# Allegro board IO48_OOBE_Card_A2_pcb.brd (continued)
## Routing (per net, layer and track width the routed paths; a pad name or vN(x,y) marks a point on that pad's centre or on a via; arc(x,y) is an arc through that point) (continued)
E_RXD0: length 7.5
  TOP w0.142: R31.2 50.72,80.03 v1(50.72,79.58) 50.72,79.15 50.64,79.07 U1.32
  BOTTOM w0.142: v1(50.72,79.58) 50.59,79.71 R32.1 51.04,80.53 51.23,80.72 51.23,82.88 51.04,83.07 R12.1
E_RXD1: length 7.6
  TOP w0.142: R29.2 v1(51.74,79.58) 51.1,78.95 51.1,78.18 51.14,78.14 U1.31
  BOTTOM w0.142: v1(51.74,79.58) 51.86,79.71 R30.1 52.31,80.53 52.5,80.72 52.5,82.88 52.31,83.07 R13.1
E_RXD2: length 7.6
  TOP w0.142: U1.28 52.64,78.96 52.75,79.07 v1(52.75,79.58) 53.01,79.83 R27.2
  BOTTOM w0.142: v1(52.75,79.58) 53.13,79.96 R28.1 53.58,80.53 53.77,80.72 53.77,82.88 53.58,83.07 R14.1
E_RXD3: length 8.1
  TOP w0.142: R25.2 54.02,80.03 54.02,79.83 v1(53.77,79.58) 53.01,78.82 53.01,78.18 53.14,78.05 U1.27
  BOTTOM w0.142: v1(53.77,79.58) 54.4,80.22 R26.1 54.85,80.53 55.04,80.72 55.04,82.88 54.85,83.07 R15.1
EN: length 3
  BOTTOM w0.127: U5.20 19.47,53.3 18.91,53.86 R5286.1
ENET_1.2V_AVDDL: length 9.6
  TOP w0.254: U1.4 v1(50.14,69.67) ; U1.9 v1(52.64,69.8)
  BOTTOM w0.381: v1(52.64,69.8) 53.01,70.17 C931.2 51.93,70.5 C23.1 50.78,70.5 C25.2 49.7,70.11 v1(50.14,69.67)
  BOTTOM w0.508: L4.2 C23.1
ENET_1.2V_AVDLL_PLL: length 6.9
  TOP w0.254: U1.44 47.02,73.38 v1(46.91,73.48)
  BOTTOM w0.508: L3.2 C18.1 45.77,71.96 46.4,72.6 C20.2 46.91,72.66 v1(46.91,73.48)
ENET_1.2V_DVDDL: length 14.2
  TOP w0.254: U1.30 v1(51.64,78.56) ; v1(56.31,73.48) 55.92,73.88 U1.18 ; U1.14 55.12,71.88 v1(55.93,71.07) ; v1(56.18,76.63) 55.93,76.38 U1.23 ; v1(53.77,78.56) 53.64,78.44 U1.26 ; v1(46.53,76.15) 46.8,75.88 U1.39
  BOTTOM w0.508: C936.2 55.55,71.45 v1(55.93,71.07) ; v1(51.64,78.56) 51.61,78.53 C932.2 ; C933.2 v1(53.77,78.56) ; v1(56.18,76.63) 56.12,76.69 C934.2 56.12,78.25 ; C935.2 56.12,73.68 v1(56.31,73.48) ; v1(46.53,76.15) 46.97,76.15 C31.2
  vias: v1(55.67,79.71)
ENET_1.8V_DVDDH: length 19.5
  TOP w0.254: U1.40 46.77,75.38 v1(46.53,75.14) ; U1.16 55.52,72.88 56.05,72.34 v1(56.44,72.34) ; U1.34 v1(49.64,78.56)
  TOP w0.381: R37.1 v1(42.85,74.88) ; R18.1 v1(58.34,70.75) ; v1(55.55,81.36) 55.36,81.17 R25.1 R27.1 R29.1 R31.1 R33.1 R35.1 47.48,81.17 v1(47.16,81.49) ; v1(59.86,76.09) R22.1
  BOTTOM w0.508: v1(46.53,75.14) 47.04,74.63 C938.2 ; C939.2 56.5,72.41 v1(56.44,72.34) ; v1(49.64,78.56) 49.7,78.5 C17.2 48.24,77.87
  vias: v1(47.55,77.68) v1(48.18,78.95)
ENET_3.3V_AVDDH: length 8.7
  TOP w0.254: U1.12 54.14,70.06 v1(54.4,69.8) ; U1.1 v1(48.64,69.72)
  BOTTOM w0.381: C937.2 54.28,69.93 v1(54.4,69.8) ; C13.2 48.43,69.93 v1(48.64,69.72)
  BOTTOM w0.508: L1.2 C11.1 55.93,69.55 54.97,70.5 C937.2
ENET_GTX_CLK: length 5.3
  BOTTOM w0.142: J1.15 19.93,67.83 20.37,67.39 21.62,67.39 R5311.2
ENET_INTN: length 35.7
  TOP w0.142: U1.38 47.32,76.38 46.91,76.79 45.64,76.79 45.13,76.28 R10.2 44.56,75.83 44.37,75.64 42.34,75.64 41.96,76.02 v1(41.96,76.79)
  L3_SIG w0.155: v1(24.3,69.29) 24.68,69.67 24.68,69.8 27.35,72.47 27.35,73.87 28.88,75.39 40.56,75.39 v1(41.96,76.79)
  BOTTOM w0.142: J1.27 19.87,70.83 20.11,71.07 22.53,71.07 v1(24.3,69.29)
ENET_LED1: length 8.2
  TOP w0.142: v1(59.8,75.2) R22.2 R23.1 58.15,74.06 57.07,72.98 56.05,72.98 55.65,73.38 U1.17
  BOTTOM w0.142: v1(59.8,75.2) 60.2,75.6 Q6.1
ENET_LED2: length 11.6
  TOP w0.142: U1.15 55.38,72.38 56.12,71.64 R18.2 R19.1 60.5,74.25 60.75,74.5 61.87,74.5 Q4.1
ENET_MDC: length 47.6
  TOP w0.142: v1(31.54,82.88) 33.45,82.88 34.62,81.71 39.32,81.71 42.59,78.44 44.37,78.44 44.56,78.63 R4.2 46.02,79.07 46.78,78.31 48.12,78.31 48.64,77.79 U1.36
  L3_SIG w0.155: v1(31.54,82.88) 30.73,82.07 30.73,81.84 30.17,81.28 27.66,81.28 25.13,78.76 23.22,78.76 22.65,78.18 18.84,78.18 17.06,76.41 11.1,76.41 10.59,75.9 v1(10.59,75.39)
  BOTTOM w0.142: J1.50 11.93,76.33 11.86,76.41 11.22,76.41 10.59,75.77 v1(10.59,75.39)
ENET_MDIO: length 34.7
  TOP w0.142: U1.37 47.33,76.88 46.53,77.68 R6.2 44.56,77.1 44.46,77 42.76,77 41.7,78.06 41.7,78.56 39.14,81.13 34.06,81.13 33.32,81.87 v1(31.54,81.87)
  L3_SIG w0.155: v1(20.24,76.15) 21,76.91 24.05,76.91 25.32,78.18 27.86,80.72 30.4,80.72 v1(31.54,81.87)
  BOTTOM w0.142: J1.49 20.06,76.33 v1(20.24,76.15)
ENET_RSET: length 4.1
  TOP w0.142: U1.48 47.39,71.38 47.08,71.07 46.45,71.07 45.82,71.71 45.2,71.71 R17.1
ENET_RSTN: length 20.1
  TOP w0.142: R5287.2 v1(31.92,81.04) ; v1(45.39,74.25) 45.51,74.12 47.04,74.12 47.29,74.38 U1.42
  BOTTOM w0.142: v1(31.92,81.04) 32.94,80.03 32.94,79.58 36.88,75.64 43.99,75.64 v1(45.39,74.25)
ENET_RX_CLK: length 58.2
  L3_SIG w0.155: v1(37.13,82.88) 41.7,82.88 41.96,82.63 41.96,82.05 41.8,81.89 39.57,81.89 39.42,81.74 39.42,81.43 39.57,81.28 41.55,81.28 41.7,81.12 41.7,80.81 41.55,80.66 39.57,80.66 39.42,80.5 39.42,80.19 39.57,80.04 40.41,80.04 40.56,79.88 40.56,78.43 40.41,78.28 39.52,78.28 39.37,78.12 39.37,77.81 39.52,77.66 40.41,77.66 40.56,77.5 40.56,76.41 40.05,75.9 28.5,75.9 26.84,74.25 26.84,72.72 22.14,68.02 v1(21,68.02)
  BOTTOM w0.142: v1(21,68.02) 20.49,68.02 20.19,68.33 J1.17 ; v1(37.13,82.88) 37.51,83.26 46.66,83.26 47.35,83.96 R8.2
ENET_RX_DV: length 58.4
  L3_SIG w0.155: v1(10.59,69.04) 10.71,68.91 11.6,68.91 12.18,69.48 12.39,69.48 13.2,68.68 13.42,68.68 13.64,68.9 13.64,69.12 12.83,69.92 12.83,70.14 13.13,70.44 14.4,70.44 14.78,70.06 16.81,70.06 17.06,69.8 18.46,69.8 18.76,70.1 18.98,70.1 19.91,69.17 20.13,69.17 20.35,69.39 20.35,69.61 19.42,70.54 19.42,70.76 19.99,71.33 23.16,71.33 24.3,72.47 24.3,73.49 24.46,73.65 24.96,73.65 25.11,73.8 25.11,74.11 24.96,74.27 24.46,74.27 24.3,74.42 24.3,74.88 28.62,79.2 33.83,79.2 34.72,80.09 v1(34.72,82.76)
  BOTTOM w0.142: J1.18 11.81,68.33 11.6,68.53 11.1,68.53 v1(10.59,69.04) ; R11.2 49.32,84.41 49.2,84.53 47.04,84.53 46.27,83.77 36.88,83.77 36.11,83.01 34.97,83.01 v1(34.72,82.76)
ENET_RXD0: length 58
  L3_SIG w0.155: v1(21,69.33) 22.69,69.33 26.21,72.85 26.21,74.63 27.99,76.41 30.02,76.41 30.91,77.29 32.3,77.29 33.07,76.53 34.3,76.53 34.45,76.69 34.45,77.27 34.61,77.42 34.92,77.42 35.07,77.27 35.07,76.69 35.23,76.53 35.54,76.53 35.69,76.69 35.69,77.27 35.85,77.42 36.16,77.42 36.31,77.27 36.31,76.69 36.47,76.53 38.78,76.53 38.91,76.66 38.91,77.27 38.75,77.42 37.97,77.42 37.77,77.63 37.77,78.4 37.92,78.56 38.75,78.56 38.91,78.71 38.91,79.02 38.75,79.18 37.92,79.18 37.77,79.33 37.77,79.64 37.92,79.8 38.75,79.8 38.91,79.95 38.91,80.26 38.75,80.42 37.92,80.42 37.77,80.57 37.77,80.88 37.92,81.04 38.5,81.04 38.66,81.19 38.66,81.5 38.5,81.66 37.92,81.66 37.77,81.81 37.77,82.09 37.61,82.25 36.9,82.25 36.75,82.4 36.75,82.5 36.11,83.14 v1(36.11,84.03)
  BOTTOM w0.142: v1(36.11,84.03) 36.37,84.28 46.02,84.28 46.78,85.04 50.32,85.04 50.59,84.77 R12.2 ; J1.21 v1(21,69.33)
ENET_RXD1: length 57.7
  L3_SIG w0.155: v1(33.7,84.03) 33.7,83.39 33.55,83.23 33.3,83.23 33.15,83.08 33.15,82.77 33.3,82.62 33.93,82.62 34.08,82.46 34.08,82.15 33.93,82 33.3,82 33.15,81.84 33.15,81.53 33.3,81.38 33.8,81.38 33.96,81.22 33.96,80.09 33.58,79.71 28.37,79.71 23.8,75.14 23.8,72.72 22.91,71.83 19.73,71.83 18.21,70.31 17.32,70.31 17.06,70.56 15.03,70.56 14.65,70.94 12.75,70.94 v1(11.35,69.55)
  BOTTOM w0.142: R13.2 51.86,85.04 51.35,85.55 46.53,85.55 45.77,84.79 35.73,84.79 35.35,84.41 35.35,83.9 34.97,83.52 34.21,83.52 v1(33.7,84.03) ; v1(11.35,69.55) 11.57,69.33 J1.22
ENET_RXD2: length 58
  L3_SIG w0.155: v1(21,70.56) 23.16,70.56 25.66,73.07 25.66,75.48 28.88,78.69 32.56,78.69 33.19,78.06 36.81,78.06 37,78.25 37,78.6 36.78,78.82 35.71,78.82 35.46,79.07 35.46,79.41 35.62,79.57 37.1,79.57 37.26,79.72 37.26,80.03 37.1,80.19 35.62,80.19 35.46,80.34 35.46,80.8 35.62,80.95 36.85,80.95 37.05,81.15 37.05,81.37 36.85,81.57 35.62,81.57 35.46,81.73 35.46,83.28 v1(34.72,84.03)
  BOTTOM w0.142: R14.2 53.13,85.42 52.5,86.06 46.4,86.06 45.64,85.3 35.23,85.3 34.72,84.79 v1(34.72,84.03) ; J1.25 20,70.33 20.24,70.56 v1(21,70.56)
ENET_RXD3: length 58.3
  L3_SIG w0.155: v1(10.59,70.06) 10.84,70.06 12.24,71.45 14.14,71.45 15.03,72.34 16.05,72.34 17.57,70.82 17.95,70.82 20.11,72.98 20.88,72.98 28.11,80.22 32.18,80.22 32.55,80.58 32.55,83.34 32.69,83.48 v1(32.69,84.03)
  BOTTOM w0.142: v1(32.69,84.03) 34.46,85.8 45.51,85.8 46.22,86.52 53.69,86.52 54.4,85.8 R15.2 ; v1(10.59,70.06) 10.84,70.06 11.11,70.33 J1.26
ENET_TX_EN: length 59.9
  TOP w0.142: v1(58.34,77.68) 57.2,77.68 55.8,79.07 54.78,79.07 54.4,78.69 54.4,78.06 54.14,77.8 U1.25
  L3_SIG w0.155: v1(58.34,77.68) 58.72,77.29 58.72,75.14 57.2,73.61 57.2,72.34 56.63,71.77 55.86,71.77 55.16,71.07 45.51,71.07 45.26,71.33 43.1,71.33 42.48,70.7 39.84,70.7 39.7,70.56 32.43,70.56 31.29,69.42 29.77,69.42 27.99,67.64 25.95,67.64 25.07,66.75 23.41,66.75 23.03,66.37 20.37,66.37 18.84,67.9 15.03,67.9 14.93,67.8 v1(14.3,67.8)
  BOTTOM w0.142: v1(14.3,67.8) 14.27,67.83 J1.16
ENET_TXD0: length 59.5
  TOP w0.142: U1.19 56.31,74.38 56.56,74.12 57.32,74.12 58.21,75.01 58.21,76.15 v1(57.58,76.79)
  L3_SIG w0.155: v1(57.58,76.79) 54.02,80.34 47.16,80.34 46.91,80.09 46.91,78.98 46.76,78.82 44.52,78.82 44.37,78.67 44.37,78.36 44.52,78.2 46.76,78.2 46.91,78.05 46.91,77.55 46.78,77.42 44.5,77.42 44.24,77.17 44.24,75.52 42.97,74.25 42.21,74.25 42.08,74.37 32.43,74.37 31.04,72.98 29,72.98 28.49,72.47 28.49,71.96 26.34,69.8 v1(26.34,69.29)
  BOTTOM w0.142: v1(26.34,69.29) 26.34,68.91 25.45,68.02 22.27,68.02 21.64,68.66 20.49,68.66 20.33,68.83 J1.19
ENET_TXD1: length 59.9
  TOP w0.142: U1.20 55.68,74.88 55.8,74.75 v1(57.07,74.75)
  L3_SIG w0.155: v1(57.07,74.75) 56.66,74.75 54.76,72.85 46.78,72.85 45.77,71.83 42.72,71.83 42.19,71.3 40.38,71.3 40.15,71.54 40.15,72.06 39.99,72.21 39.68,72.21 39.53,72.06 39.53,71.23 39.37,71.07 39.06,71.07 38.91,71.23 38.91,72.06 38.75,72.21 38.44,72.21 38.29,72.06 38.29,71.23 38.13,71.07 37.82,71.07 37.67,71.23 37.67,72.06 37.51,72.21 37.2,72.21 37.05,72.06 37.05,71.23 36.89,71.07 36.58,71.07 36.43,71.23 36.43,72.06 36.27,72.21 35.96,72.21 35.81,72.06 35.81,71.23 35.65,71.07 35.34,71.07 35.19,71.23 35.19,72.06 35.03,72.21 34.72,72.21 34.57,72.06 34.57,71.23 34.41,71.07 31.92,71.07 31.67,70.82 30.4,70.82 27.73,68.15 23.92,68.15 22.65,66.88 20.62,66.88 19.1,68.4 14.69,68.4 v1(14.27,68.83)
  BOTTOM w0.142: J1.20 v1(14.27,68.83)
ENET_TXD2: length 59.7
  TOP w0.142: U1.21 55.81,75.38 56.05,75.14 56.56,75.14 57.07,75.64 v1(57.58,75.64)
  L3_SIG w0.155: v1(25.32,69.29) 25.32,69.67 27.99,72.34 27.99,72.72 28.75,73.48 30.65,73.48 32.05,74.88 41.2,74.88 41.83,75.52 42.85,75.52 43.61,76.28 43.61,79.28 43.76,79.44 46.12,79.44 46.27,79.59 46.27,79.9 46.12,80.06 43.76,80.06 43.61,80.21 43.61,80.6 43.86,80.85 55.42,80.85 56.56,79.71 56.56,78.56 58.21,76.91 58.21,76.28 v1(57.58,75.64)
  BOTTOM w0.142: v1(25.32,69.29) 24.68,68.66 22.65,68.66 21.38,69.93 20.37,69.93 20.27,69.83 J1.23
ENET_TXD3: length 59
  TOP w0.142: v1(56.31,75.64) 56.08,75.88 U1.22
  L3_SIG w0.155: v1(56.31,75.64) 55.93,75.64 55.8,75.52 55.8,74.93 55.65,74.77 55.18,74.77 55.02,74.93 55.02,75.36 54.87,75.52 54.3,75.52 54.15,75.36 54.15,73.61 54.02,73.48 53.13,73.48 52.88,73.74 52.88,75.26 52.75,75.39 52.14,75.39 51.99,75.24 51.99,73.61 51.74,73.36 50.21,73.36 49.96,73.61 49.96,75.25 49.8,75.41 48.84,75.41 48.69,75.25 48.69,74.25 48.56,74.12 46.53,74.12 46.02,73.61 45.51,73.61 44.24,72.34 41.2,72.34 40.56,72.98 32.94,72.98 31.29,71.33 30.15,71.33 27.48,68.66 23.67,68.66 22.4,67.39 20.88,67.39 19.35,68.91 15.19,68.91 v1(14.27,69.83)
  BOTTOM w0.142: J1.24 v1(14.27,69.83)
ENET_VDD1.2V: length 7.7
  TOP w0.254: U62.2 61.71,86.56 C930.2 ; U62.1 61.26,86.06
  TOP w0.381: R699.1 v1(63.17,89.99) ; R5265.2 v1(61.9,89.99)
  BOTTOM w0.508: L4.1 v1(48.69,67.52) ; v1(41.58,72.98) 40.69,72.09 L3.1
  vias: v1(60.88,80.6) v1(61.13,81.36) v1(61.9,81.49) v1(61.9,80.6)
ENET_XI: length 3.4
  TOP w0.142: R21.2 46.53,72.34 46.56,72.38 U1.46
FPGA_JTAG_TCK: length 16.4
  L6_SIG w0.155: v1(19.61,86.57) 23.57,82.6 v1(23.57,79.3)
  BOTTOM w0.142: J1.55 19.89,77.83 20.11,78.06 R693.1 21.83,78.63 22.02,78.82 23.08,78.82 v1(23.57,79.3) ; v1(19.61,86.57) 18.98,86.57 18.91,86.5 R117.1
FPGA_JTAG_TDI: length 23.1
  TOP w0.142: R681.1 8.02,76.96 7.95,77.04 v1(7.41,77.04)
  L6_SIG w0.155: v1(13.89,88.22) 13.89,86.18 6.65,78.95 6.65,77.8 v1(7.41,77.04)
  BOTTOM w0.142: J1.56 11.89,77.83 11.35,77.29 10.65,77.29 R686.2 9.13,77.04 v1(7.41,77.04) ; R121.1 v1(13.89,88.22)
FPGA_JTAG_TDO: length 39.3
  L6_SIG w0.155: v1(7.41,78.31) 7.41,78.95 14.42,85.95 14.42,88.62 18.21,92.41 29.64,92.41 v1(31.23,90.82)
  BOTTOM w0.142: R123.1 v1(31.23,90.82) ; J1.58 11.71,78.34 11.48,78.56 10.65,78.56 R688.2 9.13,78.31 v1(7.41,78.31)
FPGA_JTAG_TMS: length 15.6
  TOP w0.142: R682.1 18.84,78.06 18.78,78.12 R687.2 18.06,78.69 v1(17.7,78.34)
  L6_SIG w0.155: v1(17.7,88.22) 17.7,85.42 18.97,84.15 18.97,80.47 17.7,79.2 v1(17.7,78.34)
  BOTTOM w0.142: R119.1 v1(17.7,88.22) ; J1.57 v1(17.7,78.34)
FT232R_3V3OUT: length 7.1
  TOP w0.254: U9.16 73.76,84.25 74.14,84.64 v1(74.14,85.14)
  BOTTOM w0.508: v1(74.14,85.14) 74.14,85.82 C55.2 73.9,86.5 74.34,86.95 C56.1 v1(75.1,85.93) ; v1(75.99,81.1) 75.55,81.1 R97.1
FT232R_RXD: length 4.3
  TOP w0.142: U9.2 70.04,78.95 69.6,78.5 68.83,78.5 67.87,77.53 U65.4
FT232R_TXD: length 3.5
  TOP w0.142: U63.2 67.89,83.37 68.12,83.14 68.12,81.88 68.25,81.75 U9.30
FT232R_VCCIO: length 20
  TOP w0.254: v1(69.39,79.08) 69.54,79.23 U9.1
  TOP w0.305: v1(75.87,80.15) R105.2
  TOP w0.381: R5284.1 v1(64.37,86.95) ; v1(67.61,80.22) C945.1 66.91,79.48 67.56,78.83 U65.5 ; v1(72.69,89.87) 71.74,89.87 R5271.1 ; U64.5 70.93,90.14 71.36,90.57 C944.1 v1(70.53,91.01)
  TOP w0.508: v1(69.1,90.92) D5.A D4.A
  BOTTOM w0.508: v1(69.39,79.08) 69.54,79.23 C57.2 69.73,79.77 70.68,78.82 C58.1 C919.1 74.15,78.82 R97.2 75.26,79.54 v1(75.87,80.15)
HPS_JTAG_TCK: length 20.9
  L6_SIG w0.155: v1(19.61,85.42) 22.65,82.37 v1(22.65,73.87)
  BOTTOM w0.142: v1(22.65,73.87) 22.08,73.29 R692.1 21.32,72.98 20.37,72.98 20.22,72.83 J1.35 ; v1(19.61,85.42) 16.94,85.42 16.43,85.93 R118.1
HPS_JTAG_TDI: length 26.4
  L6_SIG w0.155: v1(15.16,88.22) 15.16,85.68 8.68,79.2 8.68,73.99 v1(7.41,72.72)
  BOTTOM w0.142: J1.38 10.87,73.33 10.84,73.36 R689.2 9.76,73.8 9.57,73.99 8.15,73.99 7.41,73.26 v1(7.41,72.72) ; R122.1 v1(15.16,88.22)
HPS_JTAG_TDO: length 30.6
  TOP w0.142: R691.2 17.32,73.55 v1(17.54,73.33)
  L6_SIG w0.155: v1(28.43,90.38) 27.92,90.38 27.41,89.87 20.88,89.87 18.97,87.96 18.97,84.91 19.48,84.41 19.48,80.22 18.34,79.07 18.34,77.8 16.68,76.15 16.68,74.19 v1(17.54,73.33)
  BOTTOM w0.142: J1.37 v1(17.54,73.33) ; R124.1 v1(28.43,90.38)
HPS_JTAG_TMS: length 25
  L6_SIG w0.155: v1(16.43,88.22) 16.43,86.06 9.45,79.07 9.45,75.14 9.33,75.02 v1(9.33,71.33)
  BOTTOM w0.142: v1(9.33,71.33) 9.76,71.76 R690.2 10.51,72.83 J1.36 ; R120.1 v1(16.43,88.22)
HPS_LED0: length 13.5
  TOP w0.142: R681.2 9.51,77.85 10.55,78.9 12.47,78.9 12.7,79.13 Q1.1 13.67,79.77 14,79.44 14,78.45 16.62,75.83 v1(17.54,75.83)
  BOTTOM w0.142: J1.47 v1(17.54,75.83)
HPS_LED1: length 9.2
  TOP w0.142: R682.2 18.84,75.64 18.46,75.26 14.27,75.26 v1(14.2,75.33) 14.2,75.71 13.82,76.09 Q3.1
  BOTTOM w0.142: J1.46 v1(14.2,75.33)
HPS_LED2: length 7.5
  TOP w0.142: v1(11.48,75.83) 11.48,75.64 12.62,74.5 13.26,74.5 13.76,73.99 13.76,72.85 13.51,72.6 13,72.6 12.7,72.3 Q2.1
  BOTTOM w0.142: J1.48 v1(11.48,75.83)
HPS_OSC_CLK: length 2.9
  BOTTOM w0.142: J1.45 19.93,75.33 19.99,75.39 R5291.2
HPS_OSC_CLK_1.8V: length 6.3
  BOTTOM w0.508: 28.75,75.2 R131.1 ; R5309.2 31.86,76.02 C955.1 31.29,75.71 C953.2 28.56,75.71
HPS_PB0: length 13.8
  TOP w0.142: U69.4 v1(28.51,67.37)
  BOTTOM w0.142: v1(28.51,67.37) 28.5,67.39 28.5,69.67 27.99,70.18 24.56,70.18 23.08,71.66 20.17,71.66 20,71.83 J1.31
HPS_PB1: length 31.2
  TOP w0.142: v1(10.33,71.33) 11.1,70.56 11.3,70.56 12.87,68.99 12.87,68.02 14.02,66.88 15.41,66.88 16.23,66.07 17.2,66.07 17.66,65.61 20.24,65.61 22.65,68.02 28.04,68.02 28.52,68.51 30.98,68.51 31.86,67.63 31.86,66.42 32.32,65.96 U70.4
  BOTTOM w0.142: v1(10.33,71.33) 10.84,71.83 J1.32
HPS_RESETN: length 4.3
  TOP w0.142: R683.1 R7.2 21.25,77.29 21,77.55 v1(20.49,77.55)
  BOTTOM w0.142: v1(20.49,77.55) 20.28,77.33 J1.53
HPS_RESETN_1: length 4.9
  TOP w0.142: R685.1 25.7,76.02 25.95,76.28 25.95,77.55 25.7,77.8 25.5,77.8 25.17,78.13 25.17,79.09 25.28,79.2 U68.2
I2C1_SCL: length 22.4
  TOP w0.142: R695.2 14.25,72.28 v1(14.2,72.33)
  L3_SIG w0.155: v1(14.2,72.33) 9.96,72.33 8.86,73.43 8.86,83.09 7.29,84.66 J2.1
  BOTTOM w0.142: J1.34 v1(14.2,72.33)
I2C1_SDA: length 27.7
  TOP w0.142: v1(17.54,72.33) 17.47,72.41 R694.2
  L3_SIG w0.155: v1(17.54,72.33) 16.63,73.24 10,73.24 9.45,73.8 9.45,83.64 8.43,84.66 8.43,88.47 J2.2
  BOTTOM w0.142: J1.33 v1(17.54,72.33)
INTVCC: length 1.8
  TOP w0.381: U15.C3 v1(47.8,89.99)
  BOTTOM w0.381: v1(47.8,89.99) 48.17,89.99 48.29,90.12 R671.2
LINK_LED: length 29.8
  TOP w0.254: L10.2 v1(65.83,70.06)
  L6_SIG w0.254: v1(65.83,70.06) 65.83,69.42 66.09,69.17 66.09,59.77 66.98,58.88 74.98,58.88 77.64,56.21 77.64,53.14 J3.17
LOGIC0A: length 3.9
  TOP w0.142: R113.2 24.3,82.88 23.2,83.99 J8.30
LOGIC0B: length 3.6
  TOP w0.142: J8.32 22.56,83.74 23.03,83.26 R114.2
LOGIC1: length 3.7
  TOP w0.142: J8.34 21.93,84.5 22.14,84.28 22.14,83.01 21.76,82.63 R115.2
MDI_HPS_N0: length 21.9
  TOP w0.112: U1.3 49.64,70.07 49.56,69.98 49.56,67.92 56.24,61.23 56.24,58.94 59.44,55.74 60.93,55.74 61.02,55.74 61.39,56.11 J3.10
MDI_HPS_N1: length 33.4
  TOP w0.112: J3.5 63.93,56.59 64.49,57.15 65.14,57.15 65.25,57.04 65.25,56.21 65.07,56.04 65.07,55.63 65.25,55.45 65.25,55.2 65.07,55.02 65.07,54.69 65.25,54.51 65.25,53.3 64.68,52.73 63.43,52.73 62.73,53.43 62.73,54.13 62.91,54.31 62.91,54.77 62.73,54.94 62.73,56.04 62.91,56.21 62.91,56.67 62.73,56.85 62.73,57.84 62.2,58.37 59.77,58.37 58.21,59.93 58.21,60.15 57.96,60.4 57.74,60.4 57.45,60.69 57.45,61.8 51.06,68.2 51.06,69.98 51.14,70.07 U1.6
MDI_HPS_N2: length 19.3
  TOP w0.112: U1.8 52.14,70.07 52.06,69.98 52.06,69.23 59.99,61.29 59.99,60.36 60.64,59.72 61.72,59.72 62.91,60.91 63.67,60.91 63.93,61.17 J3.2
MDI_HPS_N3: length 17.8
  TOP w0.112: J3.9 62.07,61.6 62.32,61.6 62.86,62.14 62.86,65.87 61.65,67.08 55.98,67.08 53.56,69.51 53.56,69.98 53.64,70.07 U1.11
MDI_HPS_P0: length 21.9
  TOP w0.112: J3.11 60.79,55.41 59.31,55.41 55.91,58.81 55.91,61.09 49.23,67.78 49.23,69.98 49.14,70.07 U1.2
MDI_HPS_P1: length 33.5
  TOP w0.112: U1.5 50.64,70.07 50.73,69.98 50.73,68.06 57.12,61.66 57.12,60.56 59.63,58.04 62.06,58.04 62.4,57.7 62.4,53.29 63.29,52.4 64.82,52.4 65.58,53.16 65.58,57.18 65.27,57.48 64.31,57.48 J3.4
MDI_HPS_P2: length 19.2
  TOP w0.112: U1.7 51.64,70.07 51.73,69.98 51.73,69.09 59.66,61.16 59.66,60.23 60.5,59.39 61.86,59.39 63.05,60.58 63.24,60.58 J3.3
MDI_HPS_P3: length 17.8
  TOP w0.112: U1.10 53.14,70.07 53.23,69.98 53.23,69.37 55.74,66.85 55.84,66.75 56.11,66.75 61.52,66.75 62.53,65.74 62.53,62.27 62.19,61.93 61.66,61.93 61.39,62.2 J3.8
MICRO_USB_PGND:
  vias: v1(39.04,50.85) v1(39.04,49.81) v1(40.18,51.16) v1(40.15,49.94)
MICTOR_JTAG_TCK: length 12.3
  BOTTOM w0.142: R5301.1 26.4,90.82 25.45,89.87 20.18,89.87 R117.2 R118.2
MICTOR_JTAG_TDI: length 9.5
  BOTTOM w0.142: R5303.1 22.34,91.2 22.02,90.88 15.99,90.88 R122.2 R121.2
MICTOR_JTAG_TDO: length 4
  TOP w0.142: J8.11 28.91,91.1 v1(29.38,90.63)
  BOTTOM w0.142: R123.2 R124.2 29.32,91.2 29.38,91.13 v1(29.38,90.63)
MICTOR_JTAG_TMS: length 9.1
  BOTTOM w0.142: R5302.1 24.37,91.07 23.67,90.38 18.47,90.38 18.15,90.06 R119.2 R120.2
MICTOR_JTAG_TRSTN: length 6.4
  TOP w0.142: J8.21 25.74,93.26 v1(25.45,93.55)
  BOTTOM w0.142: R112.1 22.34,92.92 24.81,92.92 v1(25.45,93.55)
MICTOR_PWR1: length 3.8
  TOP w0.254: v1(29.13,84.03) 28.91,84.24 J8.12
  BOTTOM w0.508: R110.1 27.61,85.55 v1(29.13,84.03)
MICTOR_SRSTN: length 19.9
  TOP w0.142: J8.9 v1(29.55,93.51) ; v1(25.95,82.37) 25.95,80.9 25.1,80.05 25.1,79.83 24.56,79.29 24.56,77.99 R684.2
  L3_SIG w0.155: v1(25.95,82.37) 25.95,83.64 27.86,85.55 27.86,91.83 v1(29.55,93.51)
MINI_USB_PGND:
  vias: v1(78.79,90.12) v1(80.18,91.52) v1(80.18,90.12)
PB_SW0: length 32.3
  TOP w0.142: S1.2 v1(47.24,52.89) ; U69.2 27.86,62.31 27.54,61.99 R125.1 27.54,57.55 v1(26.64,56.64)
  BOTTOM w0.142: v1(47.24,52.89) 47.24,52.89 C62.2 46.47,53.36 46.25,53.57 40.05,53.57 38.25,55.37 32.99,55.37 30.96,57.41 27.4,57.41 v1(26.64,56.64)
PB_SW1: length 27.2
  TOP w0.142: U70.2 31.67,61.18 31.73,61.12 R128.1 31.73,57.44 v1(32.64,56.54) ; S2.2 v1(49.09,54.18)
  BOTTOM w0.142: v1(49.09,54.18) C63.2 48.29,53.46 47.57,54.18 40.2,54.18 38.45,55.93 33.24,55.93 v1(32.64,56.54)
PHY_25M_3.3V: length 8
  TOP w0.381: R20.1 39.11,79.71 v1(39.75,79.07) Y3.4
  BOTTOM w0.508: v1(39.75,79.07) 39.62,78.94 C925.2 C927.2 38.35,78.3 37.64,79.01 R5308.2
PWN_EN: length 41.7
  TOP w0.142: U15.D2 v1(50.34,87.45) ; U15.B2 v1(46.53,87.45)
  L3_SIG w0.152: v1(24.3,79.96) 25.57,79.96 27.35,81.74 27.35,83.64 29.43,85.73 44.8,85.73 v1(46.53,87.45) 47.16,86.82 49.7,86.82 v1(50.34,87.45)
  BOTTOM w0.142: v1(24.3,79.96) 24.68,79.58 R698.2 R5307.1 24.43,78.18 23.54,77.29 21.38,77.29 20.92,76.83 J1.51
PWR_ENA: length 1.8
  TOP w0.142: R105.1 74.71,81.44 74.27,81.44 73.95,81.75 U9.11
SD_3.3V: length 3
  TOP w0.254: 22.91,56.59 23.09,56.78 U6.A1
  BOTTOM w0.406: v1(17.06,53.99) 17.32,53.74 17.32,53.1 17.13,52.91 R66.2
  vias: v1(8.68,59.39) v1(8.68,58.5) v1(11.1,58.12) v1(12.24,57.36) v1(22.14,55.45) v1(22.14,54.56)
SD_CLK: length 25.2
  L6_SIG w0.155: v1(28.37,62.94) 25.95,65.36 25.95,67.26 25.07,68.15 24.68,68.15 23.67,69.17 23.67,71.2 22.02,72.85 22.02,74.59 21.41,75.19 20.71,75.19 v1(20.35,74.83)
  BOTTOM w0.142: v1(28.37,62.94) 28.37,61.55 28.18,61.36 R79.2 26.4,60.02 25.7,60.02 25.33,59.65 U5.10 ; v1(20.35,74.83) 19.85,74.33 J1.41
SD_CLK_3.3V: length 25
  TOP w0.142: J5.5 v1(11.01,56.93)
  L3_SIG w0.155: v1(11.6,53.42) 13.64,51.39 24.56,51.39 v1(25.32,50.62)
  BOTTOM w0.142: v1(11.6,53.42) R76.1 10.71,53.8 11.48,54.56 11.48,56.09 11.68,56.29 D3.1 12.05,56.66 11.78,56.93 v1(11.01,56.93) ; v1(25.32,50.62) 25.32,51 25.33,51.01 U5.11
SD_CMD: length 33.1
  L6_SIG w0.155: v1(10.97,74.25) 19.1,66.12 19.1,63.07 19.92,62.25 19.92,61.48 20.24,61.17 25.32,61.17 v1(27.1,62.94)
  BOTTOM w0.142: J1.40 11.38,73.83 v1(10.97,74.25) ; v1(27.1,62.94) 27.1,61.55 26.91,61.36 R80.2 25.76,60.66 25.32,60.66 24.67,60.01 U5.9
SD_CMD_3.3V: length 24.9
  TOP w0.142: J5.3 v1(13.21,56.93)
  L3_SIG w0.155: v1(13.26,53.42) 14.78,51.89 24.3,51.89 v1(25.93,53.52)
  BOTTOM w0.142: v1(13.26,53.42) R75.1 12.37,53.42 13,54.05 13,56.14 12.86,56.29 D3.2 12.43,56.78 12.58,56.93 v1(13.21,56.93) ; v1(25.93,53.52) 25.1,53.52 24.67,53.1 U5.12
SD_DATA0: length 32.5
  L6_SIG w0.155: v1(20.6,73.59) 19.92,73.59 19.76,73.43 19.76,72.24 19.61,72.09 19.3,72.09 19.15,72.24 19.15,73.43 18.99,73.59 18.49,73.59 18.34,73.43 18.34,71.73 18.62,71.45 21,71.45 21.64,70.82 21.64,70.43 21.79,70.28 22.5,70.28 22.65,70.12 22.65,69.81 22.5,69.66 21.79,69.66 21.64,69.5 21.64,69.19 21.79,69.04 22.5,69.04 22.65,68.88 22.65,68.57 22.5,68.42 21.79,68.42 21.64,68.26 21.64,67.95 21.79,67.8 22.5,67.8 22.65,67.64 22.65,67.33 22.5,67.18 22.04,67.18 21.81,66.95 21.81,66.42 21.64,66.25 21.64,64.99 21.79,64.84 22.24,64.84 22.4,64.68 22.4,64.37 22.24,64.22 21.43,64.22 21.22,64.01 21.22,63.5 21.45,63.27 21.69,63.27 v1(22.02,62.94)
  BOTTOM w0.142: v1(22.02,62.94) 22.14,62.82 22.14,61.67 21.83,61.36 R81.2 21.64,60.15 22.07,59.71 U5.5 ; J1.39 20.35,73.83 v1(20.6,73.59)
SD_DATA0_3.3V: length 24.7
  TOP w0.142: J5.7 v1(8.81,56.97)
  L3_SIG w0.155: v1(21.71,53.55) 19.08,53.55 17.48,55.15 9.33,55.15 9.01,54.83 9.01,54.36 v1(9.95,53.42)
  BOTTOM w0.142: U5.16 22.07,53.19 v1(21.71,53.55) ; v1(8.81,56.97) 8.81,55.46 8.74,55.38 D2.1 8.36,55.01 9.06,54.31 R70.1 v1(9.95,53.42)
SD_DATA1: length 33
  L6_SIG w0.155: v1(14.14,74.33) 13.75,74.33 13.56,74.15 13.56,73.69 13.76,73.48 15.92,73.48 16.94,72.47 16.94,71.07 17.67,70.34 17.89,70.34 18.43,70.88 18.65,70.88 18.87,70.66 18.87,70.44 18.33,69.9 18.33,69.68 18.55,69.46 18.77,69.46 19.31,70.01 19.53,70.01 19.75,69.79 19.75,69.57 19.2,69.03 19.2,68.81 19.42,68.59 19.64,68.59 20.18,69.13 20.4,69.13 20.62,68.91 20.62,68.69 20.08,68.15 20.08,67.93 20.24,67.77 20.24,67.32 20.39,67.16 21.02,67.16 21.18,67.01 21.18,66.7 21.02,66.55 20.39,66.55 20.24,66.39 20.24,63.71 21.64,62.31 22.65,62.31 v1(23.29,62.94)
  BOTTOM w0.142: v1(23.29,62.94) 23.29,61.55 23.1,61.36 R82.2 22.65,60.6 22.72,60.53 U5.6 ; J1.42 v1(14.14,74.33)
SD_DATA1_3.3V: length 24.9
  TOP w0.142: J5.8 7.71,56.67 v1(7.41,56.97)
  L3_SIG w0.155: v1(8.3,53.42) 8.94,52.78 10.97,52.78 13.13,50.62 v1(22.65,50.62)
  BOTTOM w0.142: v1(22.65,50.62) 22.65,51.06 22.72,51.13 U5.15 ; v1(8.3,53.42) R72.1 7.41,54.43 7.99,55.01 D2.2 7.61,55.38 7.41,55.58 v1(7.41,56.97)
SD_DATA2: length 32.3
  L6_SIG w0.155: v1(17.57,74.75) 18.08,74.25 18.36,74.25 18.52,74.4 18.52,76.63 18.67,76.79 18.98,76.79 19.14,76.63 19.14,74.4 19.29,74.25 20.75,74.25 21.38,73.61 21.38,71.96 21.51,71.83 22.27,71.83 23.16,70.94 23.16,67.04 23.32,66.89 24.15,66.89 24.3,66.73 24.3,66.42 24.15,66.27 23.32,66.27 23.16,66.11 23.16,65.51 23.32,65.36 23.8,65.36 23.92,65.23 23.92,64.09 24.05,63.96 25.04,63.96 25.19,63.81 25.19,63.2 24.94,62.94 v1(24.56,62.94)
  BOTTOM w0.142: J1.43 18.04,74.83 17.96,74.75 v1(17.57,74.75) ; v1(24.56,62.94) 24.56,61.55 24.37,61.36 R83.2 23.37,60.81 U5.7
SD_DATA2_3.3V: length 24.2
  TOP w0.142: J5.1 15.41,57.1 v1(15.79,57.48)
  L3_SIG w0.155: v1(16.56,53.42) 17.06,52.91 17.48,52.91 17.66,53.09 17.66,53.44 17.93,53.71 18.26,53.71 18.49,53.48 18.49,53.05 18.63,52.91 22.11,52.91 22.4,53.2 22.4,54.03 22.81,54.43 22.81,55.83 23.08,56.11 23.36,56.11 23.68,55.79 23.68,54.07 v1(23.16,53.55)
  BOTTOM w0.142: v1(16.56,53.42) R73.1 15.67,55.45 15.22,55.9 D1.1 15.59,56.27 15.79,56.47 v1(15.79,57.48) ; U5.14 23.37,53.33 v1(23.16,53.55)
SD_DATA3: length 33
  L6_SIG w0.155: v1(25.83,62.94) 24.68,61.8 21.26,61.8 19.61,63.45 19.61,67.64 19.08,68.17 18.86,68.17 18.57,67.88 18.35,67.88 18.13,68.1 18.13,68.32 18.42,68.61 18.42,68.82 18.2,69.04 17.98,69.04 17.7,68.76 17.48,68.76 17.26,68.97 17.26,69.19 17.55,69.48 17.55,69.7 16.43,70.82 16.43,72.09 15.54,72.98 13.33,72.98 v1(11.48,74.83)
  BOTTOM w0.142: v1(25.83,62.94) 25.83,61.55 25.64,61.36 R84.2 24.02,60.19 U5.8 ; J1.44 v1(11.48,74.83)
SD_DATA3_3.3V: length 24.9
  TOP w0.142: J5.2 v1(14.31,57.44)
  L3_SIG w0.155: v1(24.18,53.55) 24.18,54.74 24.42,54.98 25.07,54.98 25.33,54.71 25.33,53.62 24.11,52.4 15.92,52.4 v1(14.91,53.42)
  BOTTOM w0.142: v1(14.91,53.42) R74.1 14.02,53.42 14.46,53.86 R78.2 14.84,55.45 D1.2 14.6,56.27 14.31,56.55 v1(14.31,57.44) ; v1(24.18,53.55) 24.02,53.39 U5.13
SD_RSTN: length 27.4
  TOP w0.127: U6.B2 24.81,58.88 R5306.1 25.76,59.71 v1(26.08,59.39)
  TOP w0.142: R5289.2 32.18,75.71 v1(32.18,69.42)
  BOTTOM w0.142: v1(32.18,69.42) 31.54,68.79 30.27,68.79 29.31,67.82 29.31,61.84 26.86,59.39 v1(26.08,59.39)
TRACECTL: length 4.1
  TOP w0.142: J8.36 21.29,83.12 20.67,82.5 20.56,82.5 R116.2
UART_RESETN: length 5
  TOP w0.142: U9.18 72.54,85.3 72.54,85.82 72.18,86.18 71.76,86.18 R5270.2 71.93,87.04 71.93,88.15 R5271.2
UART_RSTN: length 46.9
  TOP w0.142: v1(29.89,81.87) R5290.2 ; v1(68.88,89.99) 68.37,89.49 U64.2
  L3_SIG w0.155: v1(29.89,81.87) 29.89,82.37 29.77,82.5 29.77,84.66 30.15,85.04 53.39,85.04 57.96,89.61 60.37,89.61 61.52,90.76 68.12,90.76 v1(68.88,89.99)
UART_RX: length 67.6
  TOP w0.142: R5300.1 63.12,82.07 63.93,81.26 R5283.2 59.55,79.9 v1(56.56,82.88) ; v1(29.89,77.04) 28.62,75.77 28.62,73.1 26.72,71.2 20.24,71.2 18.09,69.05 17.9,69.05 R696.2 17.51,68.21 17.32,68.02 16.05,68.02 15.67,68.4 15.67,70.69 v1(15.03,71.33)
  L6_SIG w0.155: v1(29.89,77.04) 32.66,79.81 35.59,79.81 39.18,83.39 54.02,83.39 55.16,82.25 55.93,82.25 v1(56.56,82.88)
  BOTTOM w0.142: J1.30 v1(15.03,71.33)
UART_RX_LED: length 2
  TOP w0.142: R104.1 71.04,85.89 U9.21
UART_TX: length 60.5
  TOP w0.142: v1(29,77.55) 29,77.04 27.99,76.02 27.99,73.73 26.09,71.83 19.86,71.83 18.34,70.31 R697.2 17.51,71.26 v1(17.7,71.45) ; U65.2 64.18,78.18 63.93,78.44 R5283.1 63.36,79.01 63.04,79.33 59.23,79.33 v1(55.67,82.88)
  L6_SIG w0.155: v1(55.67,82.88) 54.53,84.03 39.04,84.03 35.48,80.47 31.92,80.47 v1(29,77.55)
  BOTTOM w0.142: v1(17.7,71.45) 17.82,71.33 J1.29
UART_TX_LED: length 2.2
  TOP w0.142: U9.22 70.54,85.37 R103.1
USB_5V: length 1.3
  TOP w0.381: J4.1 31.16,54.18
  vias: v1(30.81,55.88) v1(30.81,55.02) v1(31.24,54.18) v1(31.64,55.88) v1(31.62,54.99) v1(33.19,63.07) v1(33.58,62.44) v1(34.08,63.07) v1(34.59,62.44) v1(34.97,63.07)
USB_CLK: length 34
  TOP w0.142: R59.1 v1(47.42,68.79)
  L3_SIG w0.155: v1(20.98,64.82) 22.25,64.82 23.01,64.06 29.55,64.06 32.69,67.2 32.69,67.52 33.19,68.02 33.61,68.02 34.93,69.34 34.93,69.6 35.39,70.06 40.08,70.06 40.23,70.21 42.74,70.21 43.35,70.82 44.12,70.82 44.69,70.25 46.53,70.25 47.42,69.36 v1(47.42,68.79)
  BOTTOM w0.142: J1.3 v1(20.98,64.82)
USB_CLKR: length 3.6
  TOP w0.142: U4.1 45.27,65.24 46.15,66.12 46.59,66.12 R59.2
USB_CPEN: length 12.7
  TOP w0.142: U4.17 40.67,59.66 v1(40.18,60.15) ; U3.7 38.33,67.71 v1(38.66,67.39)
  BOTTOM w0.142: v1(38.66,67.39) 39.42,67.39 40.24,66.56 40.25,66.56 40.81,66 R45.1 40.36,65.55 40.18,65.36 40.18,63.71 40.94,62.94 40.94,60.91 v1(40.18,60.15)
USB_D_N: length 16
  TOP w0.132: J4.2 31.81,51.8 32.18,51.44 34.06,51.44 34.44,51.82 35.68,51.82 42.77,58.9 U4.19
USB_D_P: length 15.9
  TOP w0.132: U4.18 42.27,59.39 42.46,59.2 42.46,59.03 42.02,58.59 41.61,58.59 41.39,58.36 41.39,57.95 41.2,57.76 40.76,57.76 40.53,57.53 40.53,57.1 40.28,56.85 39.82,56.85 39.52,56.54 39.52,56.09 35.56,52.12 34.31,52.12 33.93,51.74 32.3,51.74 32.15,51.89 32.15,52.02 32.46,52.33 J4.3
USB_DATA0: length 48.5
  TOP w0.142: R5292.1 v1(44.88,68.79)
  L3_SIG w0.155: v1(44.88,68.79) 44.88,67.67 40.57,63.36 39.61,63.36 37.66,61.41 36.18,61.41 35.78,61.8 33.32,61.8 32.81,61.29 32.81,60.4 31.67,59.26 31.39,59.26 31.23,59.42 31.23,60.25 31.08,60.4 30.77,60.4 30.61,60.25 30.61,59.42 30.46,59.26 26.97,59.26 26.21,60.02 25.7,60.02 24.94,59.26 18.08,59.26 15.83,61.51 15.61,61.51 15.2,61.09 14.98,61.09 14.76,61.31 14.76,61.53 15.18,61.95 15.18,62.17 12.01,65.33 11.86,65.48 v1(11.1,65.48)
  BOTTOM w0.142: J1.6 11.25,65.33 v1(11.1,65.48)
USB_DATA1: length 48.2
  TOP w0.142: v1(42.96,68.76) 42.96,68.48 R5293.1
  L3_SIG w0.155: v1(17.01,65.45) 16.15,64.58 15.49,64.58 15.25,64.34 15.25,63.55 18.34,60.47 21,60.47 21.71,61.18 29.74,61.18 32.9,64.34 35.3,64.34 36.01,63.64 36.01,63.03 36.5,62.54 37.46,62.54 38.43,63.5 38.43,64.13 38.64,64.34 40.13,64.34 40.47,64.67 40.47,66.06 40.99,66.58 40.99,68.71 41.39,69.1 41.97,69.1 42.31,68.76 42.31,66.63 42.48,66.46 42.93,66.46 43.46,66.98 43.46,68.27 v1(42.96,68.76)
  BOTTOM w0.142: J1.7 18.05,65.83 18.02,65.8 17.37,65.8 v1(17.01,65.45)
USB_DATA2: length 48.4
  TOP w0.142: v1(39.92,69.29) 41.83,69.29 42.34,68.79 R5294.1
  L3_SIG w0.155: v1(17.62,66.47) 17.62,67.17 17.84,67.39 18.14,67.39 18.26,67.26 18.26,66.32 18.53,66.05 18.77,66.05 18.97,66.25 18.97,66.5 19.09,66.62 19.47,66.62 19.72,66.37 19.72,66.01 19.87,65.86 20.34,65.86 20.49,65.71 20.49,65.25 20.32,65.08 20.32,63.6 20.63,63.29 21,63.29 21.33,63.62 21.33,64.07 21.5,64.24 22.08,64.24 22.74,63.59 29.83,63.59 32.1,65.85 34.53,65.85 34.98,66.31 34.98,68.54 35.45,69.01 35.45,69.4 35.63,69.57 36.94,69.57 37.16,69.36 37.16,66.21 37.33,66.03 37.69,66.03 37.69,66.06 37.8,66.17 37.8,69.29 37.99,69.48 39.07,69.48 39.3,69.26 39.3,67.3 39.54,67.07 39.76,67.07 39.92,67.24 v1(39.92,69.29)
  BOTTOM w0.142: v1(17.62,66.47) 17.77,66.33 J1.9
USB_DATA3: length 48.5
  TOP w0.142: R5295.1 41.07,67.87 v1(41.63,68.43)
  L3_SIG w0.155: v1(41.63,68.43) 41.63,66.2 41.04,65.61 41.04,64.6 40.29,63.85 39.43,63.85 37.54,61.95 36.37,61.95 35.53,62.79 35.53,63.24 35.14,63.63 32.99,63.63 30.02,60.66 30.02,60.15 29.64,59.77 28.55,59.77 28.39,59.92 28.39,60.38 28.24,60.53 27.93,60.53 27.77,60.38 27.77,59.92 27.62,59.77 27.23,59.77 26.46,60.53 25.45,60.53 24.68,59.77 24.4,59.77 24.25,59.92 24.25,60.5 24.09,60.66 23.78,60.66 23.63,60.5 23.63,59.92 23.47,59.77 22.74,59.77 22.58,59.92 22.58,60.55 22.43,60.71 22.12,60.71 21.96,60.55 21.96,59.92 21.81,59.77 18.34,59.77 11.98,66.12 11.6,66.12 v1(10.97,66.75)
  BOTTOM w0.142: J1.10 11.65,66.33 11.22,66.75 v1(10.97,66.75)
USB_DATA4: length 48
  TOP w0.142: R5296.1 39.8,68.53 39.42,68.91 37.77,68.91 37.64,69.04 37.64,69.55 37.51,69.67 37.15,69.67 37.01,69.53 37.01,69.18 36.87,69.04 36.58,69.04 36.44,69.18 36.44,69.53 36.3,69.67 36.01,69.67 35.87,69.53 35.87,69.18 35.73,69.04 35.44,69.04 35.3,69.18 35.3,69.53 35.16,69.67 v1(34.21,69.67)
  L3_SIG w0.155: v1(22.27,65.61) 22.65,65.23 23.29,65.23 23.54,65.48 23.54,66.09 23.7,66.25 24.02,66.25 24.18,66.09 24.18,65.48 24.43,65.23 25.34,65.23 25.62,65.51 25.62,66.65 25.84,66.88 26.08,66.88 26.24,66.73 26.24,65.13 26.39,64.98 26.7,64.98 26.86,65.13 26.86,66.91 27.03,67.08 27.25,67.08 27.39,66.94 27.39,64.9 27.69,64.59 28.03,64.59 28.18,64.75 28.18,66.6 28.34,66.75 28.65,66.75 28.8,66.6 28.8,64.7 28.95,64.55 29.36,64.55 29.51,64.7 29.51,66.02 29.86,66.36 31.05,66.36 31.25,66.57 31.25,66.77 31.04,66.98 31.04,66.98 29.54,66.98 29.33,67.19 29.33,67.75 30.02,68.44 30.02,68.79 30.15,68.91 30.53,68.91 30.65,68.79 30.65,68.4 30.78,68.28 31.16,68.28 31.29,68.41 31.29,68.76 31.44,68.91 31.77,68.91 31.92,68.76 31.92,68.28 32.12,68.08 32.46,68.08 32.81,68.43 32.81,69.85 32.94,69.98 33.91,69.98 v1(34.21,69.67)
  BOTTOM w0.142: J1.11 21.06,66.83 v1(22.27,65.61)
USB_DATA5: length 48.6
  TOP w0.142: v1(36.75,59.39) 36.75,61.04 36.11,61.67 36.11,63.96 36.37,64.21 R5297.1
  L3_SIG w0.155: v1(36.75,59.39) 36.75,58.88 36.5,58.63 33.45,58.63 32.52,57.7 16.47,57.7 16.07,58.1 15.67,58.1 14.99,58.78 14.77,58.78 14.62,58.63 14.4,58.63 14.18,58.84 14.18,59.06 14.33,59.22 14.33,59.44 14.11,59.66 13.9,59.66 13.74,59.5 13.52,59.5 13.08,59.95 13.08,61.98 12.24,62.82 10.33,62.82 9.83,63.33 9.83,63.54 9.99,63.71 9.99,63.93 9.77,64.14 9.55,64.14 9.39,63.98 9.17,63.98 8.94,64.21 v1(8.94,67.39)
  BOTTOM w0.142: v1(8.94,67.39) 11.22,67.39 11.79,66.83 J1.12
USB_DATA6: length 48.7
  TOP w0.142: R5298.1 37.51,62.94 37.38,62.82 37.38,61.69 37.24,61.55 36.94,61.55 36.61,61.87 36.61,63.26 v1(37.04,63.69)
  L3_SIG w0.155: v1(37.04,63.69) 37.04,64.91 36.58,65.37 32.37,65.37 29.31,62.31 20.88,62.31 19.75,63.43 19.75,65.34 19.6,65.48 18.46,65.48 18.34,65.61 17.71,65.61 17.08,66.25 15.54,66.25 15.03,65.74 15.03,64.85 14.78,64.59 14.53,64.59 14.27,64.85 14.27,66.12 14.14,66.25 12.62,66.25 11.07,67.8 11.07,68.07 11.3,68.3 12.76,68.3 13.12,67.95 13.13,67.95 14.07,67.01 15.21,67.01 15.53,67.33 v1(16.68,67.33)
  BOTTOM w0.142: J1.13 v1(16.68,67.33)
USB_DATA7: length 48.8
  TOP w0.142: v1(38.96,60.3) 38.34,60.92 R5299.1
  L3_SIG w0.155: v1(9.83,68.02) 8.81,68.02 8.3,67.52 8.3,63.58 8.82,63.07 8.82,62.85 8.21,62.24 8.21,62.02 8.43,61.8 8.65,61.8 9.25,62.41 9.47,62.41 10.84,61.04 11.93,61.04 12.4,60.57 12.4,58.59 14.14,56.85 16.3,56.85 16.65,57.19 32.77,57.19 33.58,57.99 37.16,57.99 38.96,59.79 v1(38.96,60.3)
  BOTTOM w0.142: v1(9.83,68.02) 11.22,68.02 11.92,67.33 J1.14
USB_DIR: length 47.8
  TOP w0.142: R61.1 v1(48.88,66.37)
  L3_SIG w0.155: v1(17.74,64.95) 18.1,64.59 18.49,64.59 18.82,64.26 18.82,63.3 19.95,62.17 19.95,61.25 20.2,61 20.71,61 21.51,61.8 29.51,61.8 32.6,64.89 35.57,64.89 36.51,63.95 36.51,63.27 36.71,63.07 37.25,63.07 37.87,63.69 37.87,64.46 38.25,64.84 39.68,64.84 39.97,65.12 39.97,66.31 40.46,66.8 40.46,68.9 41.22,69.66 43.19,69.66 43.43,69.42 46.4,69.42 46.78,69.04 46.78,67.96 48.37,66.37 v1(48.88,66.37)
  BOTTOM w0.142: J1.5 18.11,65.33 v1(17.74,64.95)
USB_DIRR: length 2.2
  TOP w0.142: U4.31 46.52,63.31 46.78,63.58 47.29,63.58 47.42,63.71 R61.2
USB_ID: length 17.9
  TOP w0.142: v1(33.11,54.01) J4.4 ; v1(44.65,56.39) 45.26,57 45.26,58.51 44.77,59 U4.23
  L3_SIG w0.155: v1(33.11,54.01) 33.11,54.89 33.78,55.55 35.94,55.55 36.77,56.39 v1(44.65,56.39)
USB_NXT: length 48.5
  TOP w0.142: R60.1 v1(46.15,68.79)
  L3_SIG w0.155: v1(46.15,68.79) 45.79,68.43 45.79,67.79 40.89,62.89 39.89,62.89 37.52,60.53 35.48,60.53 34.72,59.77 32.94,59.77 31.92,58.75 17.83,58.75 16.3,60.28 15.03,60.28 14.21,61.1 14.21,62.37 11.98,64.59 11.1,64.59 10.08,65.61 v1(10.08,66.12)
  BOTTOM w0.142: J1.8 11.52,65.83 11.22,66.12 v1(10.08,66.12)
USB_NXTR: length 3.1
  TOP w0.142: U4.2 44.77,65.56 R60.2
USB_RBIAS: length 1.7
  TOP w0.254: U4.24 45.27,59.13 45.89,58.5 R63.2
USB_RSTN: length 34.4
  TOP w0.127: U4.27 46.51,61.31 46.78,61.04 47.29,61.04 v1(47.93,61.67)
  TOP w0.142: R5288.2 v1(32.18,77.99)
  L6_SIG w0.155: v1(47.93,61.67) 48.56,62.31 48.56,63.96 46.02,66.5 41.96,66.5 40.56,67.9 40.56,73.41 v1(42.08,74.93)
  BOTTOM w0.142: v1(32.18,77.99) 33.77,77.99 36.83,74.93 v1(42.08,74.93)
USB_STP: length 51.3
  TOP w0.142: v1(47.93,62.82) 47.42,62.31 U4.29
  L3_SIG w0.155: v1(47.93,62.82) 48.55,62.19 48.55,60.91 48.17,60.53 46.77,60.53 45.77,61.53 45.77,61.55 44.71,61.55 44.71,61.55 42.13,61.55 42.13,61.55 41.7,61.55 41.45,61.8 39.62,61.8 37.77,59.95 36.55,59.95 35.73,59.13 33.19,59.13 32.27,58.21 16.72,58.21 16.24,58.69 15.73,58.69 13.64,60.78 13.64,62.18 11.98,63.83 11.1,63.83 v1(10.08,64.85)
  BOTTOM w0.142: J1.4 10.1,64.82 v1(10.08,64.85)
USB_UART_5V: length 9.9
  TOP w0.254: v1(71.98,85.65) 72.04,85.59 U9.19
  TOP w0.508: L6.1 v1(72.64,88.93)
  BOTTOM w0.305: v1(71.98,85.65) 73.89,83.74 U10.6
  BOTTOM w0.508: v1(71.98,85.65) 71.89,85.74 C59.2 71.17,87.27 C60.1 72.18,87.39 72.64,87.85 v1(72.64,88.93)
USB_UART_CON_5V: length 5.8
  TOP w0.508: L6.2 C61.2 74.99,87.19 C920.1 76.25,85.93 76.41,85.93 J7.1
USB_UART_DM: length 6.9
  TOP w0.132: U9.15 73.69,83.65 74.74,83.65 C53.1 v1(75.79,84) 79.31,84 J7.2
  BOTTOM w0.132: U10.1 75.53,83.74 v1(75.79,84)
USB_UART_DP: length 7
  TOP w0.132: J7.3 77.47,82.66 77.29,82.48 77.14,82.48 76.7,82.91 76.7,83.57 76.58,83.69 76.39,83.69 76.22,83.52 76.22,83.39 v1(75.82,82.98) C54.1 74.71,83.35 73.69,83.35 U9.14
  BOTTOM w0.132: U10.2 75.56,83.24 v1(75.82,82.98)
USB_VBAT: length 12.5
  TOP w0.254: v1(43.1,58.5) 43.27,58.67 U4.20 ; U4.21 43.77,58.01 v1(43.84,57.95)
  BOTTOM w0.508: C35.2 43.84,59.05 v1(43.84,57.95) ; C35.2 43.34,59.32 43.1,59.08 v1(43.1,58.5) ; C35.2 45.77,59.32 C34.1 47.86,59.58 C914.1 R47.2
USB_VBUS: length 2.2
  TOP w0.254: v1(44.62,57.57) v1(44.62,58.31) 44.62,58.42 44.27,58.78 U4.22
  vias: v1(39.29,59.13) v1(40.18,59.13)
USB_VDD18: length 9.3
  TOP w0.254: U4.28 46.9,61.81 v1(47.04,61.67) ; U4.30 46.9,62.81 v1(47.04,62.94)
  BOTTOM w0.508: C36.2 46.34,63.39 45.77,63.96 C916.1 46.4,65.23 47.67,65.23 R44.2 ; C36.2 v1(47.04,62.94) ; C36.2 C38.2 v1(47.04,61.67)
USB_VDDIO: length 5.2
  TOP w0.254: v1(41.68,65.26) 41.68,65.07 41.77,64.98 U4.8 ; U4.11 40.68,62.81 40.18,62.31 v1(40.18,62.31) ; U4.14 40.32,61.31 v1(40.18,61.17) ; U4.32 46.25,63.81 46.66,64.21 v1(47.04,64.21)
  BOTTOM w0.508: v1(47.04,64.21) 47.55,63.71 C37.2
  vias: v1(33.65,60.33) v1(34.82,61.09) v1(35.61,59.9) v1(35.68,61.12)
USB_VFLAGN: length 29.6
  TOP w0.142: U3.2 33.95,67.71 33.58,68.09 R675.2 31.4,69.24 28.34,69.24 27.8,68.7 22.44,68.7 20.75,67.01 17.32,67.01 17.06,66.75 16.3,66.75 14.83,68.23 14.83,70.12 14.39,70.56 12.11,70.56 v1(11.35,71.33)
  BOTTOM w0.142: v1(11.35,71.33) 11.85,70.83 J1.28
USB_XI: length 5.9
  TOP w0.142: U4.26 46.38,60.81 46.53,60.66 R62.1 48.81,60.78 C41.1 51.42,60.78 Y1.1
USB_XO: length 8.4
  TOP w0.142: Y1.3 53.39,58.82 52.37,59.83 50.66,59.83 50.47,59.64 C40.1 49.45,59.64 49.32,59.77 R62.2 48.27,59.77 47.73,60.31 U4.25
VREF_B: length 6
  BOTTOM w0.305: U5.19 20.12,50.76 19.86,50.5 C46.2
  BOTTOM w0.406: C46.2 R66.1 18.02,52.4 17.95,52.47 R5286.2
N134005839: length 6.1
  TOP w0.305: R101.1 77.45,80.85 78.55,80.85 79.37,81.68 J7.4
N134005899: length 11
  TOP w0.254: D4.C 66.59,93.55 65.96,92.92 65.96,87.58 66.72,86.82 68.28,86.82 68.88,87.42 R103.2
N134005901: length 8.9
  TOP w0.254: D5.C 67.34,91.9 66.59,91.15 66.59,87.96 67.1,87.45 67.87,87.45 68.5,88.09 69.73,88.09 R104.2
N134009559: length 4
  TOP w0.142: v1(33.45,67.26) 33.65,67.06 U3.3
  BOTTOM w0.142: R42.1 31.8,66.22 32.84,67.26 v1(33.45,67.26)
N134057943: length 16.9
  BOTTOM w0.508: R73.2 R74.2 R75.2 R76.2 R70.2 R72.2 6.78,51.01 6.14,51.64 6.14,53.67 6.65,54.18 6.65,57.65 R67.2
N134062955: length 3
  TOP w0.142: J8.8 30.18,84.5 30.4,84.28 v1(30.4,83.9)
  BOTTOM w0.142: v1(30.4,83.9) 30.91,84.41 R107.2
N134063078: length 2.8
  TOP w0.254: J8.14 v1(28.28,83.52)
  BOTTOM w0.508: R111.1 v1(28.28,83.52)
N134063167: length 5.1
  TOP w0.142: v1(29.13,83.01) 29.77,83.64 29.77,84.28 29.55,84.5 J8.10
  BOTTOM w0.142: R109.2 29.77,85.11 29.77,83.64 v1(29.13,83.01)
N134106197: length 1.4
  TOP w0.381: R126.2 7.06,79.24 D6.A
N134106201: length 2.2
  TOP w0.381: Q1.3 9.45,80.72 9.23,80.94 D6.C
N134106389: length 1.4
  TOP w0.381: D8.A 7.06,73.52 R129.2
N134106393: length 3.7
  TOP w0.381: Q3.3 9.65,77.04 9.43,76.83 9.43,75.4 9.25,75.22 D8.C
N134106834: length 1.4
  TOP w0.381: R127.2 7.71,68.6 7.74,68.57 D7.A
N134106836: length 3.7
  TOP w0.381: Q2.3 9.59,72.6 8.43,71.43 D7.C
N134121389: length 1.8
  BOTTOM w0.381: Y2.1 28.08,72.82 28.11,72.79 R131.2
N134121395: length 1.7
  BOTTOM w0.142: R5291.1 23.41,75.39 23.44,75.42 Y2.3
N134242750: length 1.8
  TOP w0.381: U15.C4 v1(47.8,91.26)
  BOTTOM w0.381: v1(47.8,91.26) 47.93,91.39 R667.2
N134242873: length 1.8
  TOP w0.381: U15.C5 v1(47.8,92.53)
  BOTTOM w0.381: R612.1 47.93,92.66 v1(47.8,92.53)
N134242878: length 2
  TOP w0.381: U15.A3 v1(45.26,89.99)
  BOTTOM w0.381: v1(45.26,89.99) 45.18,90.07 C922.1
N134242888: length 1.6
  TOP w0.381: U15.E3 v1(51.61,89.99)
  BOTTOM w0.508: C921.1 v1(51.61,89.99)
N134243679: length 1.3
  BOTTOM w0.508: R668.2 R456.1
N134244009: length 2
  TOP w0.381: U15.A4 v1(45.26,91.26)
  BOTTOM w0.381: R669.2 44.69,91.34 44.76,91.26 v1(45.26,91.26)
N134244011: length 1.3
  BOTTOM w0.381: R670.2 R669.1
N134244826: length 1.8
  TOP w0.381: U15.E4 v1(51.61,91.26)
  BOTTOM w0.508: R456.2 51.1,91.77 v1(51.61,91.26)
N134266858: length 2.9
  TOP w0.142: R683.2 R685.2 R684.1
N134303911: length 3.2
  TOP w0.254: R5262.1 56.73,88.46 56.73,87.82 56.99,87.56 U62.7
N134304469: length 1.9
  TOP w0.254: U62.6 57.44,88.06 57.25,88.26 57.25,89.25 C929.2
N134306474: length 3.9
  TOP w0.254: R699.2 R39.2 C930.1 61.46,87.26 61.26,87.06 U62.3
N134306486: length 1.7
  TOP w0.254: R5265.1 61.05,87.56 U62.4
N134320476: length 2.2
  TOP w0.142: U64.4 70.28,88.84 70.66,88.46 70.66,88.18 R5270.1
N134322722: length 6.2
  TOP w0.142: v1(28.28,93.55) J8.13
  BOTTOM w0.142: R5275.1 31.67,92.47 29.36,92.47 v1(28.28,93.55)
N134323149: length 3.4
  TOP w0.142: v1(31.54,83.9) 31.29,83.9 30.82,84.37 J8.6
  BOTTOM w0.142: v1(31.54,83.9) 32.18,84.53 R5276.2
N134323985: length 5.7
  TOP w0.142: R5290.1 R5289.1 ; R5289.1 28.94,78.88 28.61,78.55 U68.4 ; R5289.1 R5288.1 R5287.1
N134344647: length 2.1
  TOP w0.142: U4.10 40.56,63.31 40.55,63.32 39.61,63.32 R5298.2
N134344648: length 2.5
  TOP w0.142: U4.4 43.77,66.12 43.61,66.28 R5293.2
N134344649: length 3.5
  TOP w0.142: R5295.2 41.64,66.37 42.21,66.37 42.77,65.82 U4.6
N134344650: length 2.1
  TOP w0.142: U4.9 40.26,63.81 39.86,64.21 R5297.2
N134344651: length 2.7
  TOP w0.142: R5292.2 44.27,66.33 U4.3
N134344652: length 1.9
  TOP w0.142: R5299.2 39.68,61.67 39.74,61.74 40.42,61.74 40.49,61.81 U4.13
N134344653: length 2.9
  TOP w0.142: U4.5 43.27,66.01 R5294.2
N134344654: length 4.1
  TOP w0.142: R5296.2 40.88,65.86 41.96,65.86 42.27,65.55 U4.7
N134352854: length 1.6
  TOP w0.142: R5300.2 63.57,84.01 63.57,84.02 U63.4
N134353275: length 3
  TOP w0.142: J8.15 27.64,91.17 v1(27.1,90.63)
  BOTTOM w0.142: v1(27.1,90.63) 27.29,90.82 R5301.2
N134353287: length 4.1
  TOP w0.142: J8.17 27.01,93.27 v1(27.26,93.52)
  BOTTOM w0.142: R5302.2 25.51,91.77 v1(27.26,93.52)
N134353299: length 5.2
  TOP w0.142: J8.19 v1(26.37,93.55)
  BOTTOM w0.142: v1(26.37,93.55) 25.1,92.28 23.73,92.28 R5303.2
N134367002: length 7.5
  TOP w0.381: R5304.2 61.9,71.9 61.9,73.27 Q4.3 62.02,73.6 62.76,74.34 64.91,74.34 65.07,74.5 65.68,74.5 Q5.1
N134368065: length 3.8
  TOP w0.381: R20.2 37.19,77.74 36.88,77.42 Y3.1
N134368399: length 5.7
  BOTTOM w0.381: R5305.2 61.9,71.9 61.9,73.27 Q6.3 62.02,73.6 62.76,74.34 63.82,74.34 64.88,75.4 Q7.1
N134420239: length 1.6
  BOTTOM w0.254: L9.1 Q7.3
N134420387: length 1.6
  TOP w0.254: Q5.3 L10.1
N134420624: length 30.6
  TOP w0.254: R16.2 C964.2 v1(64.56,70.06)
  L6_SIG w0.254: J3.16 76.88,55.96 74.6,58.24 66.59,58.24 65.45,59.39 65.45,68.9 65.2,69.16 65.2,69.42 v1(64.56,70.06)
N134420965: length 33.1
  BOTTOM w0.254: R9.2 C965.1 65.2,70.25 65.2,69.17 65.45,68.91 65.45,59.39 66.59,58.24 74.98,58.24 77.64,60.91 77.64,64.62 J3.14
N134431006: length 53.8
  TOP w0.142: v1(55.04,78.44) 54.79,78.19 U1.24
  L3_SIG w0.155: v1(55.04,78.44) 55.04,76.31 54.88,76.15 54.3,76.15 54.15,76.31 54.15,77.68 53.9,77.93 52.92,77.93 52.77,77.78 52.77,76.05 52.61,75.9 52.3,75.9 52.15,76.05 52.15,77.65 51.99,77.8 50.75,77.8 50.63,77.68 50.63,76.05 50.47,75.9 50.16,75.9 50.01,76.05 50.01,77.04 49.88,77.17 48.26,77.17 47.85,76.76 47.85,75.54 47.69,75.39 47.38,75.39 47.23,75.54 47.23,76.76 47.07,76.91 45.01,76.91 44.75,76.66 44.75,73.74 43.99,72.98 42.59,72.98 41.7,73.87 32.69,73.87 30.91,72.09 30.15,72.09 v1(27.35,69.29)
  BOTTOM w0.142: R5311.1 24.56,65.66 24.74,65.48 25.42,65.48 27.35,67.41 v1(27.35,69.29)
N1340630246: length 6.6
  TOP w0.142: v1(30.4,93.55) 30.18,93.33 J8.7
  BOTTOM w0.142: R106.1 34.4,92.47 33.83,93.04 30.91,93.04 v1(30.4,93.55)
N1343681570: length 3.9
  TOP w0.142: R21.1 Y3.3

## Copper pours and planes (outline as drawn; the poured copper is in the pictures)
GND on TOP (solid shape): 76.63,93.55 76.63,90.88 75.1,90.88 73.83,92.15 73.83,93.55 74.09,93.8 76.37,93.8
GND on TOP (solid shape): 53.9,76.53 53.9,71.83 53.77,71.71 49.07,71.71 48.94,71.83 48.94,76.53 49.07,76.66 53.77,76.66
GND on TOP (solid shape): 72.82,83.9 72.82,81.1 72.69,80.98 69.9,80.98 69.77,81.1 69.77,83.9 69.9,84.03 72.69,84.03
GND on TOP (solid shape): 25.32,56.59 25.32,54.56 24.94,54.18 24.05,54.18 23.67,54.56 23.67,56.85 25.07,56.85
GND on TOP (solid shape): 23.54,62.05 23.54,60.66 19.22,60.66 18.97,60.91 18.97,62.05 19.22,62.31 23.29,62.31
GND on TOP (solid shape): 10.31,57.84 10.31,56.63 10.31,56.63 10.31,54.69 9.57,54.69 9.57,56.85 8.81,57.61 8.81,57.86 9.06,58.12 10.03,58.12
GND on TOP (solid shape): 36.24,54.82 36.24,54.43 35.99,54.18 34.21,54.18 33.96,53.93 33.58,53.93 33.58,54.69 33.96,55.07 35.99,55.07
GND on TOP (solid shape): 48.87,51.54 48.87,49.66 48.54,49.33 45.97,49.33 45.64,49.66 45.64,51.64 45.94,51.95 48.46,51.95
GND on TOP (solid shape): 55.79,88.15 55.99,88.15 56.27,87.87 56.27,87.38 56.16,87.26 53.48,87.26 53.13,87.61 53.13,88.98 53.39,89.23 54.71,89.23
GND on TOP (solid shape): 28.24,54.31 27.48,53.55 26.84,53.55 25.95,54.43 25.95,55.7 26.34,56.09 28.24,56.09
GND on TOP (solid shape): 6.52,55.45 6.52,54.05 6.91,53.67 7.54,53.67 7.54,53.04 7.92,52.66 20.75,52.66 20.75,49.61 20.37,49.23 5.76,49.23 5.51,49.48 5.51,55.45 5.76,55.7 6.27,55.7
GND on TOP (solid shape): 73.2,93.55 73.2,92.03 75.61,89.61 75.61,88.09 74.34,88.09 74.09,87.84 73.45,87.84 73.45,89.99 72.69,90.76 72.69,91.32 72.44,91.57 71.59,91.57 71.17,91.99 71.17,93.42 71.67,93.93 72.82,93.93
GND on TOP (solid shape): 48.23,88.86 48.64,88.86 48.88,89.11 49.26,89.11 49.45,88.91 49.45,88.54 49.21,88.3 49.21,87.88 49.45,87.64 49.45,87.33 49.2,87.07 49.2,85.93 50.34,84.79 50.34,83.26 47.04,83.26 47.04,84.79 47.67,85.42 47.67,87.07 47.42,87.33 47.42,87.64 47.66,87.88 47.66,88.3 47.42,88.54 47.42,88.91 47.61,89.11 47.99,89.11
GND on TOP (solid shape): 60.31,90.59 60.31,89.16 59.86,88.71 59.86,87.25 59.85,87.22 59.81,87.2 59.74,87.2 59.74,82.3 59.72,82.26 59.69,82.25 58.34,82.25 57.96,82.63 57.96,84.96 58.47,85.47 58.47,87.07 58.39,87.07 58.35,87.09 58.34,87.12 58.34,88.64 57.68,89.3 57.68,89.42 57.5,89.6 57.5,90.11 57.45,90.11 57.42,90.12 57.4,90.16 57.4,90.67 57.58,90.85 60.05,90.85
GND on TOP (solid shape): outline of 114 points within 5.63,59.9 15.03,66.5
GND on BOTTOM (solid shape): 7.79,66.12 7.79,62.82 5.89,62.82 5.51,63.2 5.51,66.25 5.76,66.5 7.41,66.5
GND on BOTTOM (solid shape): 13.38,59.13 13.38,58.75 11.6,58.75 10.51,59.85 9.42,59.85 9.42,60.78 11.73,60.78
GND on BOTTOM (solid shape): 48.69,58.12 48.69,56.85 47.93,56.09 45.64,56.09 45.26,56.47 45.26,58.24 48.56,58.24
GND on BOTTOM (solid shape): 76.63,93.55 76.63,93.17 74.85,91.39 74.85,90.88 73.58,90.88 73.58,93.3 74.09,93.8 76.37,93.8
GND on BOTTOM (solid shape): 48.97,51.54 48.97,49.56 48.64,49.23 45.18,49.23 44.85,49.56 44.85,51.59 45.13,51.87 48.64,51.87
GND on BOTTOM (solid shape): 25.7,81.87 25.7,80.47 23.92,80.47 22.65,79.2 22.53,79.2 22.53,79.71 23.54,80.72 23.54,82.12 25.45,82.12
GND on BOTTOM (solid shape): 61.52,89.62 61.52,83.52 60.88,82.88 58.21,82.88 57.83,83.26 57.83,85.42 56.65,86.6 56.65,90.72 56.97,91.04 60.11,91.04
GND on BOTTOM (solid shape): 40.18,87.71 41.45,87.71 41.45,86.18 40.18,86.18 40.17,86.18 37.26,86.18 37.13,86.31 37.13,86.69 37.38,86.95 38.4,86.95 39.42,87.96 39.92,87.96
GND on BOTTOM (solid shape): 44.62,64.09 45.64,63.07 45.64,61.17 44.5,60.02 42.34,60.02 41.96,60.4 41.96,64.85 42.21,65.1 44.62,65.1
GND on BOTTOM (solid shape): 39.04,68.79 39.04,68.28 38.78,68.02 37.89,68.02 37.64,67.77 37.64,67.01 36.83,66.2 35.68,66.2 35.48,65.99 35.48,64.72 34.46,64.72 34.34,64.59 32.94,64.59 32.94,65.86 34.08,67.01 34.08,68.53 34.59,69.04 38.78,69.04
GND on BOTTOM (solid shape): 55.42,73.48 55.8,73.1 55.8,72.6 55.16,72.6 54.91,72.34 54.91,71.45 54.66,71.2 52.75,71.2 51.86,72.09 50.85,72.09 49.96,71.2 47.93,71.2 47.55,71.58 47.55,73.99 47.93,74.37 47.93,76.28 48.81,77.17 54.28,77.17 54.66,77.55
GND on BOTTOM (solid shape): 72.06,88.72 70.53,88.72 70.02,88.22 70.02,86.57 70.41,86.18 70.41,85.42 70.79,85.04 71.8,85.04 73.45,83.39 73.45,82.25 73.71,81.99 73.71,79.96 70.66,79.96 70.15,80.47 68.63,80.47 68.12,80.98 66.47,80.98 65.45,81.99 65.45,88.98 65.96,89.49 69.26,89.49 69.64,89.87 72.06,89.87
